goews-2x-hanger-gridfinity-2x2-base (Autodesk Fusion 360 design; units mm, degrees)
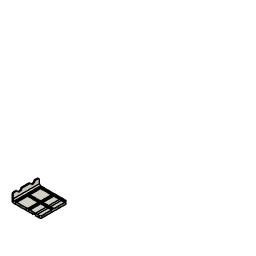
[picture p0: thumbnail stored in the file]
base_feature "Base Feature4"
base_feature "Base Feature1" bodies "Double Plate Blank", "Double Plate Gridfinity 1x2"
fillet "Fillet1" radius 3
copy_paste_bodies "CutPasteBodies"
align "Align1"
align "Align2"
align "Align3"
move "Move1"
move "Move2"
copy_paste_bodies "CopyPasteBodies2"
move "Move3"
combine "Combine1" bodies "Grid"
sketch "Sketch1" plane through (0, 0, -172.1244) normal (0, 0, -1) x axis (1, 0, 0)
  line L1 (99.15, -62.8) -> (96.15, -62.8)
  line L2 (99.15, 20.8) -> (99.15, -62.8)
  line L3 (96.15, 20.8) -> (99.15, 20.8)
  line L4 (96.15, 15.3) -> (96.15, 20.8)
  line L5 (96.15, -15.3) -> (96.15, 15.3)
  line L6 (96.15, -26.7) -> (96.15, -15.3)
  line L7 (96.15, -57.3) -> (96.15, -26.7)
  line L8 (96.15, -62.8) -> (96.15, -57.3)
  line L9 (141.15, 18.1536) -> (107.15, 18.1536)
  line L10 (142.3036, -17) -> (142.3036, 17)
  line L11 (107.15, -18.1536) -> (141.15, -18.1536)
  line L12 (105.9964, 17) -> (105.9964, -17)
  line L13 (145.15, 17) -> (145.15, -17)
  line L14 (107.15, 21) -> (141.15, 21)
  line L15 (103.15, -17) -> (103.15, 17)
  line L16 (103.15, -59) -> (103.15, -25)
  line L17 (141.15, -63) -> (107.15, -63)
  line L18 (145.15, -25) -> (145.15, -59)
  line L19 (141.15, -23.8464) -> (107.15, -23.8464)
  line L20 (142.3036, -59) -> (142.3036, -25)
  line L21 (107.15, -60.1536) -> (141.15, -60.1536)
  line L22 (105.9964, -25) -> (105.9964, -59)
  line L23 (107.0494, 20.9987) -> (99.15, 20.8)
  line L24 (107.0494, -62.9987) -> (99.15, -62.8)
  arc A1 centre (107.15, 17) radius 1.1536 clockwise from (105.9964, 17) to (107.15, 18.1536)
  arc A2 centre (141.15, 17) radius 1.1536 clockwise from (141.15, 18.1536) to (142.3036, 17)
  arc A3 centre (141.15, -17) radius 1.1536 clockwise from (142.3036, -17) to (141.15, -18.1536)
  arc A4 centre (107.15, -17) radius 1.1536 clockwise from (107.15, -18.1536) to (105.9964, -17)
  arc A5 centre (141.15, -25) radius 4 clockwise from (141.15, -21) to (145.15, -25)
  arc A6 centre (141.15, -17) radius 4 clockwise from (145.15, -17) to (141.15, -21)
  arc A7 centre (141.15, 17) radius 4 clockwise from (141.15, 21) to (145.15, 17)
  arc A8 centre (107.15, 17) radius 4 clockwise from (103.15, 17) to (107.15, 21)
  arc A9 centre (107.15, -17) radius 4 clockwise from (107.15, -21) to (103.15, -17)
  arc A10 centre (107.15, -25) radius 4 clockwise from (103.15, -25) to (107.15, -21)
  arc A11 centre (107.15, -59) radius 4 clockwise from (107.15, -63) to (103.15, -59)
  arc A12 centre (141.15, -59) radius 4 clockwise from (145.15, -59) to (141.15, -63)
  arc A13 centre (107.15, -25) radius 1.1536 clockwise from (105.9964, -25) to (107.15, -23.8464)
  arc A14 centre (141.15, -25) radius 1.1536 clockwise from (141.15, -23.8464) to (142.3036, -25)
  arc A15 centre (141.15, -59) radius 1.1536 clockwise from (142.3036, -59) to (141.15, -60.1536)
  arc A16 centre (107.15, -59) radius 1.1536 clockwise from (107.15, -60.1536) to (105.9964, -59)
  point P4 (99.15, 20.8)
  point P48 (99.15, 20.8)
  point P49 (107.0494, 20.9987)
  point P3 (99.15, -62.8)
  point P50 (99.15, -62.8)
  point P51 (107.0494, -62.9987)
  coincident P4 P48
  coincident A8 P49
  tangent A8 L23
  coincident P3 P50
  coincident A11 P51
  tangent A11 L24
extrude "Extrude1" add sketch "Sketch1" profile of L2 A8 L15 A9 A10 L16 A11 L23 L24 against normal blind 4.646 bodies "Grid (1)"
chamfer "Chamfer1" distance 4
sketch "Sketch2" plane through (0, 0, -172.1244) normal (0, 0, -1) x axis (1, 0, 0)
  line L1 (141.15, -23.8464) -> (107.15, -23.8464)
  line L2 (142.3036, -59) -> (142.3036, -25)
  line L3 (107.15, -60.1536) -> (141.15, -60.1536)
  line L4 (105.9964, -25) -> (105.9964, -59)
  line L5 (141.15, 18.1536) -> (107.15, 18.1536)
  line L6 (142.3036, -17) -> (142.3036, 17)
  line L7 (107.15, -18.1536) -> (141.15, -18.1536)
  line L8 (105.9964, 17) -> (105.9964, -17)
  line L9 (99.15, -62.8) -> (96.15, -62.8)
  line L10 (107.0494, -62.9987) -> (99.15, -62.8)
  line L11 (141.15, -63) -> (107.15, -63)
  line L12 (145.15, -25) -> (145.15, -59)
  line L13 (145.15, 17) -> (145.15, -17)
  line L14 (107.15, 21) -> (141.15, 21)
  line L15 (99.15, 20.8) -> (107.0494, 20.9987)
  line L16 (96.15, 20.8) -> (99.15, 20.8)
  line L17 (96.15, 15.3) -> (96.15, 20.8)
  line L18 (96.15, -15.3) -> (96.15, 15.3)
  line L19 (96.15, -26.7) -> (96.15, -15.3)
  line L20 (96.15, -57.3) -> (96.15, -26.7)
  line L21 (96.15, -62.8) -> (96.15, -57.3)
  line L22 (145.15, -25) -> (145.15, -17)
  arc A1 centre (107.15, -25) radius 1.1536 clockwise from (105.9964, -25) to (107.15, -23.8464)
  arc A2 centre (141.15, -25) radius 1.1536 clockwise from (141.15, -23.8464) to (142.3036, -25)
  arc A3 centre (141.15, -59) radius 1.1536 clockwise from (142.3036, -59) to (141.15, -60.1536)
  arc A4 centre (107.15, -59) radius 1.1536 clockwise from (107.15, -60.1536) to (105.9964, -59)
  arc A5 centre (107.15, 17) radius 1.1536 clockwise from (105.9964, 17) to (107.15, 18.1536)
  arc A6 centre (141.15, 17) radius 1.1536 clockwise from (141.15, 18.1536) to (142.3036, 17)
  arc A7 centre (141.15, -17) radius 1.1536 clockwise from (142.3036, -17) to (141.15, -18.1536)
  arc A8 centre (107.15, -17) radius 1.1536 clockwise from (107.15, -18.1536) to (105.9964, -17)
  arc A9 centre (107.15, -59) radius 4 clockwise from (107.15, -63) to (107.0494, -62.9987)
  arc A10 centre (141.15, -59) radius 4 clockwise from (145.15, -59) to (141.15, -63)
  arc A11 centre (141.15, -25) radius 4 clockwise from (141.15, -21) to (145.15, -25)
  arc A12 centre (141.15, -17) radius 4 clockwise from (145.15, -17) to (141.15, -21)
  arc A13 centre (141.15, 17) radius 4 clockwise from (141.15, 21) to (145.15, 17)
  arc A14 centre (107.15, 17) radius 4 clockwise from (107.0494, 20.9987) to (107.15, 21)
  point P34 (145.15, -17)
  point P45 (145.15, -17)
  point P32 (145.15, -25)
  point P46 (145.15, -25)
  coincident P34 P45
  coincident P32 P46
extrude "Extrude2" add sketch "Sketch2" profile of A11 A12 L22 against normal blind 4.646
move_face "MoveFace1"
move_face "MoveFace2"
sketch "Sketch3" plane through (0, 0, -172.1244) normal (0, 0, -1) x axis (1, 0, 0)
  line L1 (141.15, -23.8464) -> (107.15, -23.8464)
  line L2 (142.3036, -59) -> (142.3036, -25)
  line L3 (107.15, -60.1536) -> (141.15, -60.1536)
  line L4 (105.9964, -25) -> (105.9964, -59)
  line L5 (141.15, 18.1536) -> (107.15, 18.1536)
  line L6 (142.3036, -17) -> (142.3036, 17)
  line L7 (107.15, -18.1536) -> (141.15, -18.1536)
  line L8 (105.9964, 17) -> (105.9964, -17)
  line L9 (99.15, -62.8) -> (96.15, -62.8)
  line L10 (107.0494, -62.9987) -> (99.15, -62.8)
  line L11 (141.15, -63) -> (107.15, -63)
  line L12 (145.15, 17) -> (145.15, -59)
  line L13 (107.15, 21) -> (141.15, 21)
  line L14 (99.15, 20.8) -> (107.0494, 20.9987)
  line L15 (96.15, 20.8) -> (99.15, 20.8)
  line L16 (96.15, 15.1) -> (96.15, 20.8)
  line L17 (96.15, -15.1) -> (96.15, 15.1)
  line L18 (96.15, -26.9) -> (96.15, -15.1)
  line L19 (96.15, -57.1) -> (96.15, -26.9)
  line L20 (96.15, -62.8) -> (96.15, -57.1)
  arc A1 centre (107.15, -25) radius 1.1536 clockwise from (105.9964, -25) to (107.15, -23.8464)
  arc A2 centre (141.15, -25) radius 1.1536 clockwise from (141.15, -23.8464) to (142.3036, -25)
  arc A3 centre (141.15, -59) radius 1.1536 clockwise from (142.3036, -59) to (141.15, -60.1536)
  arc A4 centre (107.15, -59) radius 1.1536 clockwise from (107.15, -60.1536) to (105.9964, -59)
  arc A5 centre (107.15, 17) radius 1.1536 clockwise from (105.9964, 17) to (107.15, 18.1536)
  arc A6 centre (141.15, 17) radius 1.1536 clockwise from (141.15, 18.1536) to (142.3036, 17)
  arc A7 centre (141.15, -17) radius 1.1536 clockwise from (142.3036, -17) to (141.15, -18.1536)
  arc A8 centre (107.15, -17) radius 1.1536 clockwise from (107.15, -18.1536) to (105.9964, -17)
  arc A9 centre (107.15, -59) radius 4 clockwise from (107.15, -63) to (107.0494, -62.9987)
  arc A10 centre (141.15, -59) radius 4 clockwise from (145.15, -59) to (141.15, -63)
  arc A11 centre (141.15, 17) radius 4 clockwise from (141.15, 21) to (145.15, 17)
  arc A12 centre (107.15, 17) radius 4 clockwise from (107.0494, 20.9987) to (107.15, 21)
extrude "Extrude3" add sketch "Sketch2" + "Sketch1" profile of S2:A1 S2:L9 S2:A2 S2:L10 S2:A3 S2:L11 S2:A4 S2:L12 S2:A13 S2:L19 S2:A14 S2:L20 S2:A15 S2:L21 S2:A16 S2:L22 S1:A1 S1:L1 S1:A2 S1:L2 S1:A3 S1:L3 S1:A4 S1:L4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 blind 2.354
delete_face "DeleteFace1"
split "Split1" bodies "Double Plate Gridfinity 1x2 (1)"
combine "Combine2"
combine "Combine3" bodies "Double Plate Gridfinity 1x2"
chamfer "Chamfer2" distance 4
extrude "Extrude4" cut sketch "Reconstructed-Sketch4" blind -1060
combine "Combine4"
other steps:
base_feature "Base Feature2" bodies "Grid"
base_feature "Base Feature3" bodies "Grid", "Grid (1)"
named bodies: "Double Plate Blank", "Double Plate Gridfinity 1x2", "Grid", "Grid (1)", "Double Plate Gridfinity 1x2 (1)"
